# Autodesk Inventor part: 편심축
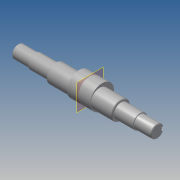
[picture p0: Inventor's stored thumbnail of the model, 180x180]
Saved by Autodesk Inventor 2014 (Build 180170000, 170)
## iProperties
Created: 2015-10
Part Number: 편심축
Document SubType Name: Modeling
Designer: mdu
Density: 1 g/cm^3
Material: 강철, 연강
Mass: 168.947 g
Surface Area: 248.524 cm^2
Volume: 168.947 cm^3
Appearance: 강철
Author: mdu
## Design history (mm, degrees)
sketch "스케치1"
  geometry: L1 (-20.5, -41.331)-(-20.5, 32.669) reference; L2 (7.5, -30.031)-(7.5, 21.369) reference; L3 (135.5, -30.331)-(135.5, 21.669) reference; L4 (121.5, 21.369)-(121.5, -30.031) reference; L5 (184.5, -4.331)-(-57.5, -4.331); L6 (184.5, -4.331)-(184.5, 6.669); L7 (154.5, 8.169)-(121.5, 8.169); L8 (121.5, 8.169)-(121.5, 11.669); L9 (121.5, 11.669)-(7.5, 11.669); L10 (7.5, 11.669)-(7.5, 8.169); L11 (7.5, 8.169)-(-27.5, 8.169); L12 (-27.5, 8.169)-(-27.5, 6.669); L13 (-27.5, 6.669)-(-57.5, 6.669); L14 (-57.5, 6.669)-(-57.5, -4.331); L15 (154.5, 8.169)-(154.5, 6.669); L16 (154.5, 6.669)-(184.5, 6.669); C1 r 32.5 at (64.5, -4.331) reference; 1 further point
  constraints: 24 end point, 8 perpendicular, 5 point on line, 3 parallel, 2 collinear
  dimensions: "d1" = 25 diameter of L11 L5; "d2" = 32 diameter of L9 L5; "d3" = 22 diameter of L13 L5; "d4" = 35 distance of L10.end L11.end; "d5" = 30 distance of L12.end L13.end; "d15" = 33 distance of L7.start L7.end; "d26" = 30 distance of L15.end L6.end
revolve "회전1" sketch "스케치1" stored, may be unused: angle "d6" = 90 deg
node "작업 평면1"
sketch "스케치2"
  geometry: C1 r 16 at (0, 0) reference; C2 r 20.75 at (0, 4)
  constraints: 1 centre point, 1 vertical alignment
  dimensions: "d34" = 4 distance of C2.centre C1.centre; "d35" = 41.5 diameter of C2
extrude "돌출1" join sketch "스케치2" stored distance "d9" = 40; taper "d10" = 0 deg
chamfer "모따기1" distance "d11" = 1; stored, may be unused: second distance "d12" = 2, angle "d13" = 45 deg
node "작업 평면2"
sketch "스케치3"
  geometry: L1 (-15, -10)-(-15, 10) reference; L2 (-15, 3)-(0, 3); L3 (0, -3)-(-15, -3); A1 r 3 centre (0, 0) between (0, -3) and (0, 3); 2 further points
  constraints: 4 end point, 2 perpendicular, 2 point on circle, 2 point on line, 2 tangent, 1 centre point, 1 horizontal alignment, 1 midpoint
  dimensions: "d16" = 18 dimension on A1 L1; "d17" = 6 distance between parallel lines of L3 L2
extrude "돌출2" cut sketch "스케치3" distance "d18" = 3.5; taper "d19" = 0 deg
node "작업 평면3"
node "작업 평면4"
node "솔리드1"
mirror "대칭1"
node "참조1"
node "참조2"
node "참조3"
node "참조4"
node "참조5"
other parameters: "d30" = 35
